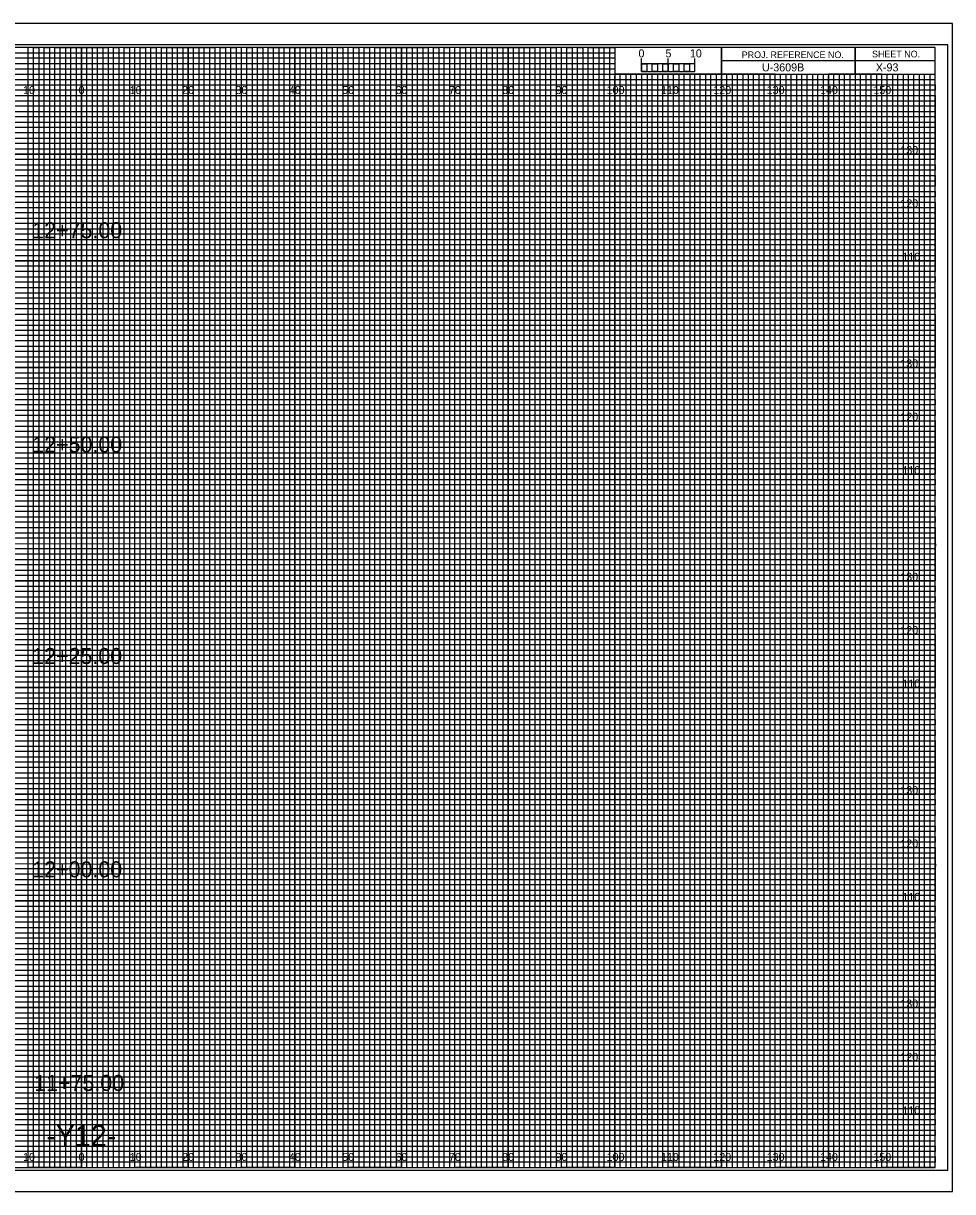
# Model space of a CAD drawing. Extents: x -13 to 323, y -5 to 874.
# Drawn here: x 149.1 to 323.3, y 215.5 to 434.5 of the extents above; entities that cross this region are included whole.
import ezdxf

# ---------------------------------------------------------------- set-up
doc = ezdxf.new("R2010")
doc.units = 0
for name, color, linetype in [('Prop XS Alignment Label', 7, 'Continuous'), ('Prop XS Bar Scale Labels', 7, 'Continuous'), ('Prop XS Elevation Labels', 7, 'Continuous'), ('Prop XS Offset Labels', 7, 'Continuous'), ('Prop XS Project Number', 7, 'Continuous'), ('Prop XS Sheet Number', 7, 'Continuous'), ('Prop XS Station Labels', 7, 'Continuous'), ('Sheet Cross Section CELL', 7, 'Continuous'), ('Sheet Cross Section Grid Major CELL', 7, 'Continuous'), ('Sheet Cross Section Grid Middle CELL', 7, 'Continuous'), ('Sheet Cross Section Grid Minor 1 CELL', 7, 'Continuous'), ('Sheet Cross Section Grid Minor 2 CELL', 7, 'Continuous'), ('Sheet Cross Section Scale CELL', 7, 'Continuous'), ('Sheet Cutting Line CELL', 7, 'Continuous'), ('Sheet DOT Grid CELL', 7, 'Continuous'), ('Sheet Plot Border Inside CELL', 7, 'Continuous'), ('Sheet Plot Border Outside CELL', 7, 'Continuous')]:
    doc.layers.add(name, color=color, linetype=linetype)

msp = doc.modelspace()

# ---------------------------------------------------------------- linework, layer by layer
at = {"layer": 'Sheet Cross Section CELL'}
for p, q in [((305, 430), (305, 425)), ((305, 425), (305, 430)), ((280, 427.5), (280, 425)), ((320, 427.49), (280, 427.49)), ((280, 425), (320, 425))]:
    msp.add_line(p, q, dxfattribs=at)
for points in [[(320, 430), (0, 430), (0, 220), (320, 220)], [(280, 430), (260, 430), (260, 425.03), (280, 425.03)], [(320, 430), (280, 430), (280, 425), (320, 425)]]:
    msp.add_lwpolyline(points, close=True, dxfattribs=at)
at = {"layer": 'Sheet Cross Section Grid Major CELL'}
for p, q in [((150, 430), (140, 430)), ((150, 220), (150, 430)), ((170, 430), (160, 430)), ((160, 430), (160, 220)), ((170, 220), (170, 430)), ((190, 430), (180, 430)), ((180, 430), (180, 220)), ((190, 220), (190, 430)), ((210, 430), (200, 430)), ((200, 430), (200, 220)), ((210, 220), (210, 430)), ((230, 430), (220, 430)), ((220, 430), (220, 220)), ((230, 220), (230, 430)), ((250, 430), (240, 430)), ((240, 430), (240, 220)), ((250, 220), (250, 430)), ((260, 430), (260, 220)), ((270, 220), (270, 425)), ((290, 425), (280, 425)), ((280, 425), (280, 220)), ((290, 220), (290, 425)), ((310, 425), (300, 425)), ((300, 425), (300, 220)), ((310, 220), (310, 425)), ((160, 220), (150, 220)), ((180, 220), (170, 220)), ((200, 220), (190, 220)), ((220, 220), (210, 220)), ((240, 220), (230, 220)), ((260, 220), (250, 220)), ((280, 220), (270, 220)), ((300, 220), (290, 220)), ((320, 220), (310, 220)), ((320, 220), (320, 220))]:
    msp.add_line(p, q, dxfattribs=at)
for points in [[(0, 420), (320, 420), (320, 410), (0, 410)], [(0, 400), (320, 400), (320, 390), (0, 390)], [(0, 380), (320, 380), (320, 370), (0, 370)], [(0, 360), (320, 360), (320, 350), (0, 350)], [(0, 340), (320, 340), (320, 330), (0, 330)], [(0, 320), (320, 320), (320, 310), (0, 310)], [(0, 300), (320, 300), (320, 290), (0, 290)], [(0, 280), (320, 280), (320, 270), (0, 270)], [(0, 260), (320, 260), (320, 250), (0, 250)], [(0, 240), (320, 240), (320, 230), (0, 230)]]:
    msp.add_lwpolyline(points, dxfattribs=at)
at = {"layer": 'Sheet Cross Section Grid Middle CELL'}
for points in [[(145, 220), (155, 220), (155, 430), (165, 430), (165, 220), (175, 220), (175, 430), (185, 430), (185, 220), (195, 220), (195, 430), (205, 430), (205, 220), (215, 220), (215, 430), (225, 430), (225, 220), (235, 220), (235, 430), (245, 430), (245, 220), (255, 220), (255, 430), (259.93, 430), (260, 430), (260, 425), (264.99, 425), (264.99, 220), (275, 220), (275, 425), (285, 425), (285, 220), (295, 220), (295, 425), (305, 425), (305, 220), (315, 220), (315, 425)], [(0, 425), (275, 425)], [(0, 405), (320, 405), (320, 415), (0, 415)], [(0, 385), (320, 385), (320, 395), (0, 395)], [(0, 365), (320, 365), (320, 375), (0, 375)], [(0, 345), (320, 345), (320, 355), (0, 355)], [(0, 325), (320, 325), (320, 335), (0, 335)], [(0, 305), (320, 305), (320, 315), (0, 315)], [(0, 285), (320, 285), (320, 295), (0, 295)], [(0, 265), (320, 265), (320, 275), (0, 275)], [(0, 245), (320, 245), (320, 255), (0, 255)], [(0, 225), (320, 225), (320, 235), (0, 235)]]:
    msp.add_lwpolyline(points, dxfattribs=at)
at = {"layer": 'Sheet Cross Section Grid Minor 1 CELL'}
for p, q in [((0, 429), (260, 429)), ((260, 427.98), (0, 427.98)), ((260, 429), (260, 427.98)), ((0, 427), (260, 427)), ((260, 425.89), (0, 425.89)), ((260, 427), (260, 425.89)), ((0, 424), (320, 424))]:
    msp.add_line(p, q, dxfattribs=at)
for points in [[(0, 423), (270, 423), (320, 423), (320, 422), (0, 422)], [(0, 421), (320, 421), (320, 419), (0, 419)], [(0, 418), (320, 418), (320, 417), (0, 416.98)], [(0, 416), (320, 416), (320, 414), (0, 414)], [(0, 413), (320, 413), (320, 412), (0, 412)], [(0, 411), (320, 411), (320, 409), (0, 409)], [(0, 408), (320, 408), (320, 407), (0, 407)], [(0, 406), (320, 406), (320, 404), (0, 404)], [(0, 403), (320, 403), (320, 402), (0, 402)], [(0, 401), (320, 401), (320, 399), (0, 399)], [(0, 398), (320, 398), (320, 397), (0, 397)], [(0, 396), (320, 396), (320, 393.95), (320, 393), (320, 392), (0, 392)], [(0, 394), (320, 394), (320, 393), (0, 393)], [(0, 391), (320, 391), (320, 389), (0, 389.03)], [(0, 389.03), (320, 389), (320, 388), (0, 388)], [(0, 387), (320, 387), (320, 386), (0, 386)], [(0, 384), (320, 384), (320, 383), (0, 383)], [(0, 382), (320, 382), (320, 381), (0, 381)], [(-0.07, 378.89), (320, 378.89), (320, 377.88), (-0.07, 377.88)], [(0, 377), (320, 377), (320, 376), (0, 376)], [(0, 374), (320, 374), (320, 373), (0, 373)], [(0, 372), (320, 372), (320, 371), (0, 371)], [(0, 369), (320, 369), (320, 368), (0, 368)], [(0, 367), (320, 367), (320, 366), (0, 366)], [(0, 364), (320, 364), (320, 363), (0, 363)], [(0, 362), (320, 362), (320, 361), (0, 361)], [(0, 359), (320, 359), (319.99, 357.98), (0, 358)], [(0, 357), (320, 357), (320, 356), (0, 356)], [(0, 354), (320, 354), (320, 353), (0, 353)], [(0, 352), (320, 352), (320, 351), (0, 351)], [(0, 349), (320, 349), (320, 348), (0, 348)], [(0, 347), (320, 347), (320, 346), (0, 346)], [(0, 344), (320, 344), (320, 343), (0, 343)], [(0, 342), (320, 342), (320, 341), (0, 341)], [(0, 339), (320, 339), (320, 338), (0, 338)], [(0, 336.99), (320.07, 336.91), (320, 336), (0, 336)], [(0, 334), (320, 334), (320, 333), (0, 333)], [(0, 332), (320, 332), (320, 331), (0, 331)], [(0, 329), (320, 329), (320, 328), (0, 328)], [(0, 327), (320, 327), (320, 326), (0, 326)], [(0, 324), (320, 324), (320, 323), (0, 323)], [(0, 322), (320, 322), (320, 321), (0, 321)], [(0, 319), (320, 319), (320, 318), (0, 318)], [(0, 317), (320, 317), (320, 316), (0, 316)], [(0, 314), (320, 314), (320, 313), (0, 313)], [(0, 312), (320, 312), (320, 311), (0, 311)], [(0, 309), (320, 309), (320, 308), (0, 308)], [(0, 307), (320, 307), (320, 306), (0, 306)], [(0, 304), (320, 304), (320, 303), (0, 303)], [(0, 302), (320, 302), (320, 301), (0, 301)], [(0, 299), (320, 299), (319.99, 297.98), (0, 298)], [(0, 297), (320, 297), (320, 296), (0, 296)], [(0, 294), (320, 294), (320, 293), (0, 293)], [(0, 292), (320, 292), (320, 291), (0, 291)], [(0, 289), (320, 289), (320, 288), (0, 288)], [(0, 287), (320, 287), (320, 286), (0, 286)], [(0, 284), (320, 284), (320, 283), (0, 283)], [(0, 282), (320, 282), (320, 281), (0, 281)], [(0, 279), (320, 279), (320, 278), (0, 278)], [(0, 276.99), (320.07, 276.91), (320, 276), (0, 276)], [(0, 274), (320, 274), (320, 273), (0, 273)], [(0, 272), (320, 272), (320, 271), (0, 271)], [(0, 269), (320, 269), (320, 268), (0, 268)], [(0, 267), (320, 267), (320, 266), (0, 266)], [(0, 264), (320, 264), (320, 263), (0, 263)], [(0, 262), (320, 262), (320, 261), (0, 261)], [(0, 259), (320, 259), (320, 258), (0, 258)], [(0, 257), (320, 257), (320, 256), (0, 256)], [(0, 254), (320, 254), (320, 253), (0, 253)], [(0, 252), (320, 252), (320, 251), (0, 251)], [(0, 249), (320, 249), (320, 248), (0, 248)], [(0, 247), (320, 247), (320, 246), (0, 246)], [(0, 244), (320, 244), (320, 243), (0, 243)], [(0, 242), (320, 242), (320, 241), (0, 241)], [(0, 239), (320, 239), (320, 238), (0, 238)], [(0, 237), (320, 237), (320, 236), (0, 236)], [(0, 234), (320, 234), (320, 233), (0, 233)], [(0, 232), (320, 232), (320, 231), (0, 231)], [(0, 229), (320, 229), (320, 228), (0, 228)], [(0, 227), (320, 227), (320, 226), (0, 226)], [(0, 224), (320, 224), (320, 223), (0, 223)], [(0, 222), (320, 222), (320, 221), (0, 221)]]:
    msp.add_lwpolyline(points, dxfattribs=at)
at = {"layer": 'Sheet Cross Section Grid Minor 2 CELL'}
for p, q in [((267, 425), (266.01, 425)), ((266.01, 425), (266.01, 220)), ((267, 220), (267, 425)), ((269, 425), (268, 425)), ((268, 425), (268, 220)), ((269, 220), (269, 425)), ((266.01, 220), (265, 220)), ((268, 220), (267, 220))]:
    msp.add_line(p, q, dxfattribs=at)
for points in [[(150, 220), (151, 220), (151, 430), (152, 430), (152, 220)], [(152, 220), (153, 220), (153, 430), (154, 430), (154, 220)], [(155, 220), (156, 220), (156, 430), (157, 430), (157, 220)], [(157, 220), (158, 220), (158, 430), (159, 430), (159, 220)], [(160, 220), (161, 220), (161, 430), (162, 430), (162, 220)], [(162, 220), (163, 220), (163, 430), (164, 430), (164, 220)], [(165, 220), (166, 220), (166, 430), (167, 430), (167, 220)], [(167, 220), (168, 220), (168, 430), (169, 430), (169, 220)], [(170, 220), (171, 220), (171, 430), (172, 430), (172, 220)], [(172, 220), (173, 220), (173, 430), (174, 430), (174, 220)], [(175, 220), (176, 220), (176, 430), (177, 430), (177, 220)], [(177, 220), (178, 220), (178, 430), (179, 430), (179, 220)], [(180, 220), (181, 220), (181, 430), (182, 430), (182, 220)], [(182, 220), (183, 220), (183, 430), (184, 430), (184, 220)], [(185, 220), (186, 220), (186, 430), (187, 430), (187, 220)], [(187, 220), (188, 220), (188, 430), (189, 430), (189, 220)], [(190, 220), (191, 220), (191, 430), (192, 430), (192, 220)], [(192, 220), (193, 220), (193, 430), (194, 430), (194, 220)], [(195, 220), (196, 220), (196, 430), (197, 430), (197, 220)], [(197, 220), (198, 220), (198, 430), (199, 430), (199, 220)], [(200, 220), (201, 220), (201, 430), (202, 430), (202, 220)], [(202, 220), (203, 220), (203, 430), (204, 430), (204, 220)], [(205, 220), (206, 220), (206, 430), (207, 430), (207, 220)], [(207, 220), (208, 220), (208, 430), (209, 430), (209, 220)], [(210, 220), (211, 220), (211, 430), (212, 430), (212, 220)], [(212, 220), (213, 220), (213, 430), (214, 430), (214, 220)], [(215, 220), (216, 220), (216, 430), (217, 430), (217, 220)], [(217, 220), (218, 220), (218, 430), (219, 430), (219, 220)], [(220, 220), (221, 220), (221, 430), (222, 430), (222, 220)], [(222, 220), (223, 220), (223, 430), (224, 430), (224, 220)], [(225, 220), (226, 220), (226, 430), (227, 430), (227, 220)], [(227, 220), (228, 220), (228, 430), (229, 430), (229, 220)], [(230, 220), (231, 220), (231, 430), (232, 430), (232, 220)], [(232, 220), (233, 220), (233, 430), (234, 430), (234, 220)], [(235, 220), (236, 220), (236, 430), (237, 430), (237, 220)], [(237, 220), (238, 220), (238, 430), (239, 430), (239, 220)], [(240, 220), (241, 220), (241, 430), (242, 430), (242, 220)], [(242, 220), (243, 220), (243, 430), (244, 430), (244, 220)], [(245, 220), (246, 220), (246, 430), (247, 430), (247, 220)], [(247, 220), (248, 220), (248, 430), (249, 430), (249, 220)], [(250, 220), (251, 220), (251, 430), (252, 430), (252, 220)], [(252, 220), (253, 220), (253, 430), (254, 430), (254, 220)], [(255, 220), (256, 220), (256, 430), (257, 430), (257, 220)], [(257, 220), (258, 220), (258, 430), (259, 430), (259, 220)], [(260, 220), (261, 220), (261, 425), (262.02, 425), (262.02, 220)], [(262, 220), (263, 220), (263, 425), (263.99, 425), (263.99, 220)], [(270, 220), (270.98, 220), (270.98, 425), (272, 425), (272, 220)], [(272, 220), (273, 220), (273, 425), (274.05, 425), (274.05, 220)], [(275, 220), (276, 220), (276, 425), (277, 425), (277, 220)], [(277, 220), (278, 220), (278, 425), (279, 425), (279, 220)], [(280, 220), (281, 220), (281, 425), (282, 425), (282, 220)], [(282, 220), (283, 220), (283, 425), (284, 425), (284, 220)], [(285, 220), (286, 220), (286, 425), (287, 425), (287, 220)], [(287, 220), (288, 220), (288, 425), (289, 425), (289, 220)], [(290, 220), (291, 220), (291, 425), (292, 425), (292, 220)], [(292, 220), (293, 220), (293, 425), (294, 425), (294, 220)], [(295, 220), (296, 220), (296, 425), (297, 425), (297, 220)], [(297, 220), (298, 220), (298, 425), (299, 425), (299, 220)], [(300, 220), (301, 220), (301, 425), (302, 425), (302, 220)], [(302, 220), (303, 220), (303, 425), (304, 425), (304, 220)], [(305, 220), (306, 220), (306, 425), (307, 425), (307, 220)], [(307, 220), (308, 220), (308, 425), (309, 425), (309, 220)], [(310, 220), (311, 220), (311, 425), (312, 425), (312, 220)], [(312, 220), (313, 220), (313, 425), (314, 425), (314, 220)], [(315, 220), (316, 220), (316, 425), (317, 425), (317, 220)], [(317, 220), (318, 220), (318, 425), (319, 425), (319, 220)]]:
    msp.add_lwpolyline(points, dxfattribs=at)
at = {"layer": 'Sheet Cross Section Scale CELL'}
for p, q in [((265, 425.49), (265, 427.9)), ((265, 426.9), (265, 427.9)), ((270, 425.49), (270, 427.9)), ((275, 425.49), (275, 427.9)), ((275, 426.9), (275, 427.9))]:
    msp.add_line(p, q, dxfattribs=at)
for points in [[(275, 426.9), (265, 426.9), (265, 425.49), (275, 425.49)], [(265, 426.9), (266, 426.9), (266, 425.49), (265, 425.49)], [(267, 426.9), (268, 426.9), (268, 425.49), (267, 425.49)], [(269, 426.9), (270, 426.9), (270, 425.49), (269, 425.49)], [(271, 426.9), (272, 426.9), (272, 425.49), (271, 425.49)], [(273, 426.9), (274, 426.9), (274, 425.49), (273, 425.49)]]:
    msp.add_lwpolyline(points, close=True, dxfattribs=at)
at = {"layer": 'Sheet Cutting Line CELL'}
for p, q in [((323.3, 434.5), (-13.4, 434.5)), ((-13.4, 215.5), (323.3, 215.5))]:
    msp.add_line(p, q, dxfattribs=at)
at = {"layer": 'Sheet DOT Grid CELL'}
for p, q in [((150, 220), (150, 430)), ((160, 220), (160, 430)), ((170, 220), (170, 430)), ((180, 220), (180, 430)), ((190, 220), (190, 430)), ((200, 220), (200, 430)), ((210, 220), (210, 430)), ((220, 220), (220, 430)), ((230, 220), (230, 430)), ((240, 220), (240, 430)), ((250, 220), (250, 430)), ((260, 220), (260, 424.69)), ((270, 220), (270, 424.69)), ((280, 220), (280, 424.69)), ((290, 220), (290, 424.69)), ((300, 220), (300, 424.69)), ((310, 220), (310, 424.69)), ((0, 420), (320, 420)), ((0, 410), (320, 410)), ((0, 400), (320, 400)), ((0, 390), (320, 390)), ((0, 380), (320, 380)), ((0, 370), (320, 370)), ((0, 360), (320, 360)), ((0, 350), (320, 350)), ((0, 340), (320, 340)), ((0, 330), (320, 330)), ((0, 320), (320, 320)), ((0, 310), (320, 310)), ((0, 300), (320, 300)), ((0, 290), (320, 290)), ((0, 280), (320, 280)), ((0, 270), (320, 270)), ((0, 260), (320, 260)), ((0, 250), (320, 250)), ((0, 240), (320, 240)), ((0, 230), (320, 230))]:
    msp.add_line(p, q, dxfattribs=at)
at = {"layer": 'Sheet Plot Border Inside CELL'}
msp.add_lwpolyline([(-10.8, 219.5), (322.4, 219.5), (322.4, 430.5), (-10.8, 430.5)], close=True, dxfattribs=at)
at = {"layer": 'Sheet Plot Border Outside CELL'}
msp.add_lwpolyline([(-13.4, 215.5), (323.3, 215.5), (323.3, 434.5), (-13.4, 434.5)], close=True, dxfattribs=at)

# ---------------------------------------------------------------- texts
at = {"layer": 'Prop XS Alignment Label'}
msp.add_text('-Y12-', height=4, dxfattribs=at).set_placement((153.41, 224))
at = {"layer": 'Prop XS Bar Scale Labels'}
for s, p in [('5', (269.47, 428.12)), ('10', (274.04, 428.12))]:
    msp.add_text(s, height=1.5, dxfattribs=at).set_placement(p)
at = {"layer": 'Prop XS Elevation Labels'}
for s, p in [('130', (313.49, 410)), ('120', (313.5, 400)), ('110', (313.88, 390)), ('130', (313.49, 370)), ('120', (313.5, 360)), ('110', (313.88, 350)), ('130', (313.49, 330)), ('120', (313.5, 320)), ('110', (313.88, 310)), ('130', (313.49, 290)), ('120', (313.5, 280)), ('110', (313.88, 270)), ('130', (313.49, 250)), ('120', (313.5, 240)), ('110', (313.88, 230))]:
    msp.add_text(s, height=1.5, dxfattribs=at).set_placement(p)
at = {"layer": 'Prop XS Offset Labels'}
for s, p in [('10', (149.04, 421.25)), ('0', (159.45, 421.25)), ('0', (159.45, 421.25)), ('10', (169.04, 421.25)), ('20', (178.86, 421.25)), ('30', (188.86, 421.25)), ('40', (198.86, 421.25)), ('50', (208.86, 421.25)), ('60', (218.86, 421.25)), ('70', (228.86, 421.25)), ('80', (238.86, 421.25)), ('90', (248.86, 421.25)), ('100', (258.44, 421.25)), ('110', (268.62, 421.25)), ('120', (278.44, 421.25)), ('130', (288.44, 421.25)), ('140', (298.44, 421.25)), ('150', (308.44, 421.25)), ('10', (149.04, 221.25)), ('0', (159.45, 221.25)), ('0', (159.45, 221.25)), ('10', (169.04, 221.25)), ('20', (178.86, 221.25)), ('30', (188.86, 221.25)), ('40', (198.86, 221.25)), ('50', (208.86, 221.25)), ('60', (218.86, 221.25)), ('70', (228.86, 221.25)), ('80', (238.86, 221.25)), ('90', (248.86, 221.25)), ('100', (258.44, 221.25)), ('110', (268.62, 221.25)), ('120', (278.44, 221.25)), ('130', (288.44, 221.25)), ('140', (298.44, 221.25)), ('150', (308.44, 221.25))]:
    msp.add_text(s, height=1.5, dxfattribs=at).set_placement(p)
at = {"layer": 'Prop XS Project Number'}
msp.add_text('U-3609B', height=1.5, dxfattribs=at).set_placement((287.56, 425.5))
at = {"layer": 'Prop XS Sheet Number'}
msp.add_text('X-93', height=1.5, dxfattribs=at).set_placement((308.9, 425.5))
at = {"layer": 'Prop XS Station Labels'}
for s, p in [('12+75.00', (150.77, 394.22)), ('12+50.00', (150.77, 354.06)), ('12+25.00', (150.77, 314.41)), ('12+00.00', (150.77, 274.42)), ('11+75.00', (151.13, 234.37))]:
    msp.add_text(s, height=3, dxfattribs=at).set_placement(p)
at = {"layer": 'Sheet Cross Section CELL'}
for s, p in [('PROJ. REFERENCE NO.', (283.77, 427.99)), ('SHEET NO.', (308.19, 428.12))]:
    msp.add_text(s, height=1.25, dxfattribs=at).set_placement(p)
at = {"layer": 'Sheet Cross Section Scale CELL'}
msp.add_text('0', height=1.5, dxfattribs=at).set_placement((264.41, 428.12))

doc.saveas('drawing.dxf')
